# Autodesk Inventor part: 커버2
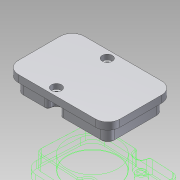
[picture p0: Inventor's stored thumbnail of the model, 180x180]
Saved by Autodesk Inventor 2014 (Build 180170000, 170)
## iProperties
Company: 한국ATC센터
Created: 2015-04
Part Number: 커버2
Document SubType Name: Modeling
Designer: KYOUNG IL JANG
Density: 2.71 g/cm^3
Material: 알루미늄-6061
Mass: 222.992 g
Surface Area: 213.51 cm^2
Volume: 82.2849 cm^3
Appearance: 매끄러움 - 흰색
Author: KYOUNG IL JANG
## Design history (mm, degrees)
node "작업 평면1"
sketch "스케치1"
  geometry: L1 (-16.986, 27.5)-(-38, 27.5) reference; L2 (-45, 20.5)-(-45, -20.5) reference; L3 (-38, -27.5)-(-16.986, -27.5) reference; L4 (0.986, -27.5)-(38, -27.5) reference; L5 (45, -20.5)-(45, 20.5) reference; L6 (38, 27.5)-(0.986, 27.5) reference; C1 r 25 at (15, 0); A1 r 3 centre (-16.986, 24.5) between (-13.991, 24.667) and (-16.986, 27.5) reference; A2 r 7 centre (-38, 20.5) between (-38, 27.5) and (-45, 20.5) reference; A3 r 7 centre (-38, -20.5) between (-45, -20.5) and (-38, -27.5) reference; A4 r 3 centre (-16.986, -24.5) between (-16.986, -27.5) and (-13.991, -24.667) reference; A5 r 6 centre (-8, -25) between (-2.009, -24.667) and (-13.991, -24.667) reference; A6 r 3 centre (0.986, -24.5) between (-2.009, -24.667) and (0.986, -27.5) reference; A7 r 7 centre (38, -20.5) between (38, -27.5) and (45, -20.5) reference; A8 r 7 centre (38, 20.5) between (45, 20.5) and (38, 27.5) reference; A9 r 3 centre (0.986, 24.5) between (0.986, 27.5) and (-2.009, 24.667) reference; A10 r 6 centre (-8, 25) between (-13.991, 24.667) and (-2.009, 24.667) reference; 1 further point
  constraints: 20 point on circle, 12 end point, 11 centre point, 4 horizontal, 2 vertical, 36 other
extrude "돌출1" new body sketch "스케치1" distance "d0" = 14; taper "d1" = 0 deg
sketch "스케치2"
  geometry: L1 (38, -32.5)-(-38, -32.5) reference; L2 (50, 20.5)-(50, -20.5) reference; L3 (-38, 32.5)-(38, 32.5) reference; L4 (-50, -20.5)-(-50, 20.5) reference; A1 r 12 centre (38, -20.5) between (38, -32.5) and (50, -20.5) reference; A2 r 12 centre (38, 20.5) between (50, 20.5) and (38, 32.5) reference; A3 r 12 centre (-38, 20.5) between (-38, 32.5) and (-50, 20.5) reference; A4 r 12 centre (-38, -20.5) between (-50, -20.5) and (-38, -32.5) reference; 1 further point
extrude "돌출2" join sketch "스케치2" distance "d2" = 7; taper "d3" = 0 deg
sketch "스케치3"
  geometry: C1 r 2.458 at (-8, 25) reference; C2 r 2.458 at (-8, -25) reference; 1 further point
hole "구멍1" sketch "스케치3" at (-8, -25), (-8, 25) diameter "d4" = 6; stored, may be unused: countersink angle "d8" = 90 deg, drill point angle "d10" = 118 deg; dims "d5" = 6, "d6" = 10, "d7" = 5, "d9" = 8
fillet "모깎기1" dims "d11" = 0.3
chamfer "모따기1" distance "d12" = 1; stored, may be unused: second distance "d13" = 2, angle "d14" = 45 deg
node "솔리드1"
node "참조2"
node "참조3"
node "참조4"
node "참조5"
node "참조6"
node "참조7"
node "참조8"
node "참조9"
node "참조10"
node "참조11"
